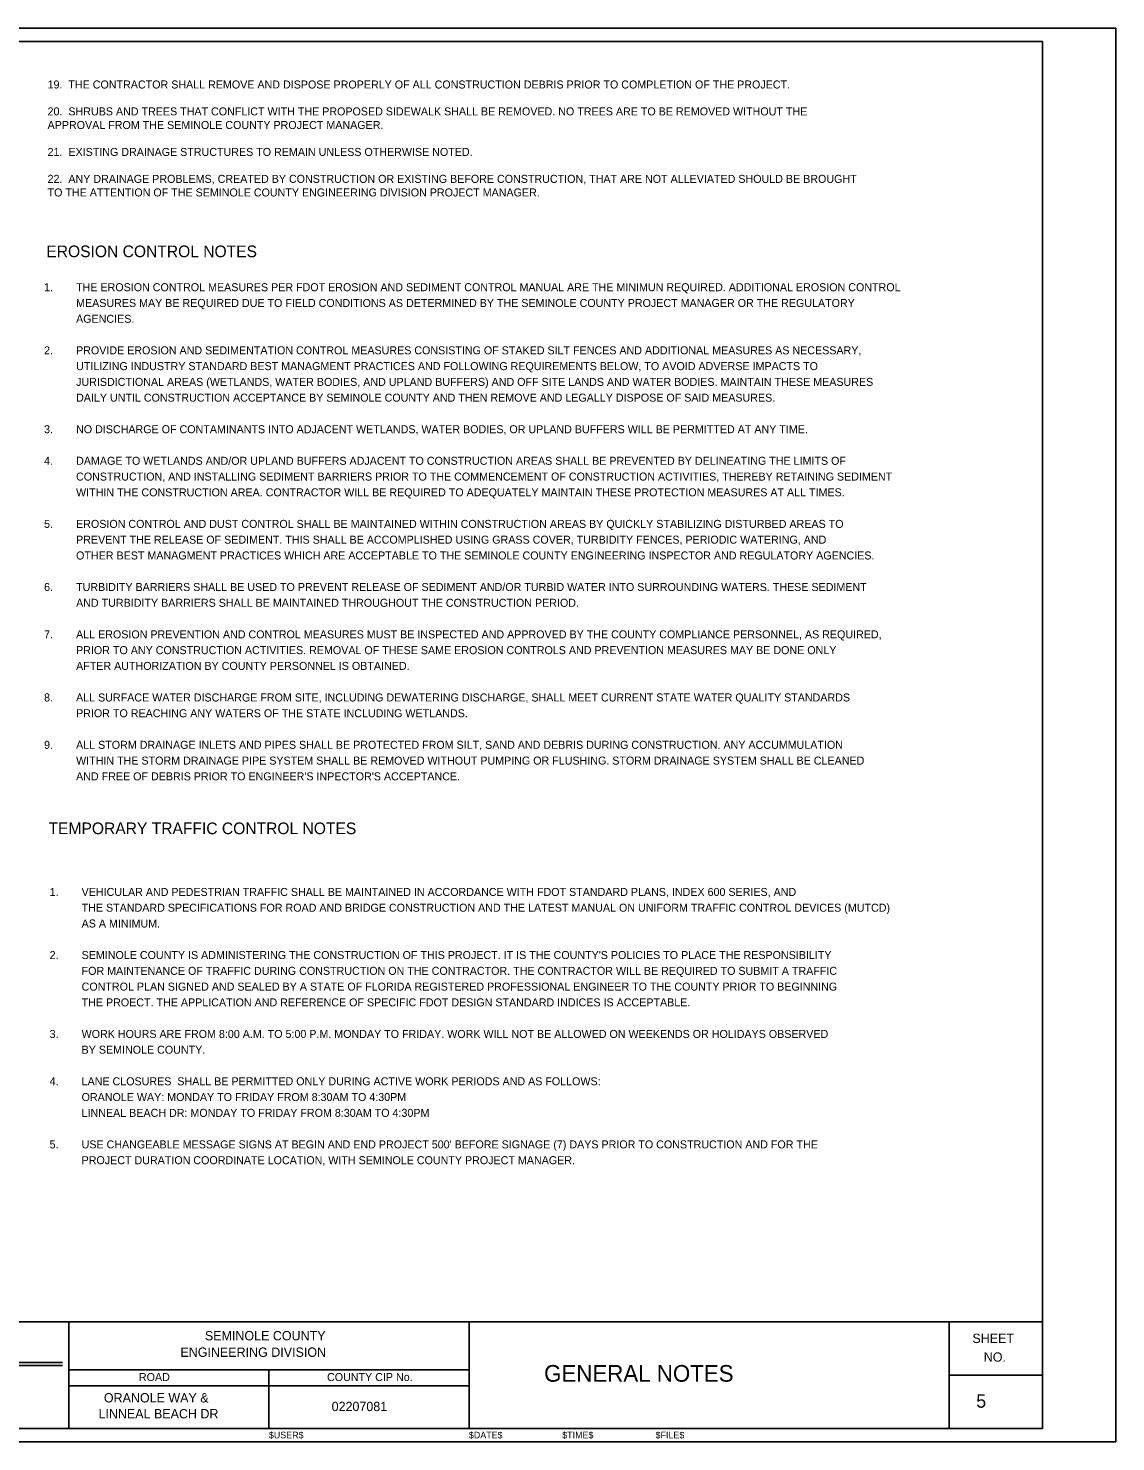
# Model space of a CAD drawing. Extents: x 9949 to 10609, y 9645 to 10069.
# Drawn here: x 10282.6 to 10608.8, y 9645.5 to 10069.5 of the extents above; entities that cross this region are included whole.
import ezdxf

# ---------------------------------------------------------------- set-up
doc = ezdxf.new("R2010")
doc.units = 0
for name, color, linetype in [('Default', 7, 'Continuous'), ('PlotBorder_dp', 7, 'Continuous'), ('SheetBorder_dp', 7, 'Continuous'), ('SheetLines_dp', 7, 'Continuous'), ('TextMinor', 7, 'Continuous'), ('TextMisc', 7, 'Continuous'), ('TextShtNo', 7, 'Continuous')]:
    doc.layers.add(name, color=color, linetype=linetype)

msp = doc.modelspace()

# ---------------------------------------------------------------- linework, layer by layer
at = {"layer": 'PlotBorder_dp'}
msp.add_lwpolyline([(9948.8, 9645.47), (10608.8, 9645.47), (10608.8, 10069.47), (9948.8, 10069.47)], close=True, dxfattribs=at)
at = {"layer": 'SheetBorder_dp'}
for p, q in [((9970.8, 10065.47), (10586.8, 10065.47)), ((10586.8, 10065.47), (10586.8, 9649.47)), ((9970.8, 9681.47), (10586.8, 9681.47)), ((9970.8, 9649.47), (10586.8, 9649.47))]:
    msp.add_line(p, q, dxfattribs=at)
at = {"layer": 'SheetLines_dp'}
for p, q in [((10294.8, 9681.47), (10294.8, 9649.47)), ((10414.8, 9649.47), (10414.8, 9681.47)), ((10558.8, 9649.47), (10558.8, 9681.47)), ((10294.8, 9667.07), (10414.8, 9667.07)), ((10354.8, 9667.07), (10354.8, 9649.47)), ((10558.8, 9665.47), (10586.8, 9665.47)), ((10294.8, 9662.27), (10414.8, 9662.27))]:
    msp.add_line(p, q, dxfattribs=at)
at = {"layer": 'TextMisc'}
for p, q in [((10237.36, 9668.35), (10292.82, 9668.35)), ((10237.44, 9669.25), (10292.9, 9669.25))]:
    msp.add_line(p, q, dxfattribs=at)

# ---------------------------------------------------------------- texts
at = {"layer": 'Default'}
for s, p in [('1. ', (10287.33, 9990.59)), ('THE EROSION CONTROL MEASURES PER FDOT EROSION AND SEDIMENT CONTROL MANUAL ARE THE MINIMUN REQUIRED. ADDITIONAL EROSION CONTROL', (10296.93, 9990.59)), ('MEASURES MAY BE REQUIRED DUE TO FIELD CONDITIONS AS DETERMINED BY THE SEMINOLE COUNTY PROJECT MANAGER OR THE REGULATORY', (10296.93, 9985.86)), ('AGENCIES.', (10296.93, 9981.12)), ('2.', (10287.33, 9971.66)), ('PROVIDE EROSION AND SEDIMENTATION CONTROL MEASURES CONSISTING OF STAKED SILT FENCES AND ADDITIONAL MEASURES AS NECESSARY, ', (10296.93, 9971.66)), ('UTILIZING INDUSTRY STANDARD BEST MANAGMENT PRACTICES AND FOLLOWING REQUIREMENTS BELOW, TO AVOID ADVERSE IMPACTS TO ', (10296.93, 9966.92)), ('JURISDICTIONAL AREAS (WETLANDS, WATER BODIES, AND UPLAND BUFFERS) AND OFF SITE LANDS AND WATER BODIES. MAINTAIN THESE MEASURES ', (10296.93, 9962.19)), ('DAILY UNTIL CONSTRUCTION ACCEPTANCE BY SEMINOLE COUNTY AND THEN REMOVE AND LEGALLY DISPOSE OF SAID MEASURES.', (10296.93, 9957.46)), ('3.', (10287.33, 9947.99)), ('NO DISCHARGE OF CONTAMINANTS INTO ADJACENT WETLANDS, WATER BODIES, OR UPLAND BUFFERS WILL BE PERMITTED AT ANY TIME.', (10296.93, 9947.99)), ('4. ', (10287.33, 9938.52)), ('DAMAGE TO WETLANDS AND/OR UPLAND BUFFERS ADJACENT TO CONSTRUCTION AREAS SHALL BE PREVENTED BY DELINEATING THE LIMITS OF', (10296.93, 9938.52)), ('CONSTRUCTION, AND INSTALLING SEDIMENT BARRIERS PRIOR TO THE COMMENCEMENT OF CONSTRUCTION ACTIVITIES, THEREBY RETAINING SEDIMENT', (10296.93, 9933.79)), ('WITHIN THE CONSTRUCTION AREA. CONTRACTOR WILL BE REQUIRED TO ADEQUATELY MAINTAIN THESE PROTECTION MEASURES AT ALL TIMES.', (10296.93, 9929.06)), ('5.', (10287.33, 9919.59)), ('EROSION CONTROL AND DUST CONTROL SHALL BE MAINTAINED WITHIN CONSTRUCTION AREAS BY QUICKLY STABILIZING DISTURBED AREAS TO', (10296.93, 9919.59)), ('PREVENT THE RELEASE OF SEDIMENT. THIS SHALL BE ACCOMPLISHED USING GRASS COVER, TURBIDITY FENCES, PERIODIC WATERING, AND ', (10296.93, 9914.86)), ('OTHER BEST MANAGMENT PRACTICES WHICH ARE ACCEPTABLE TO THE SEMINOLE COUNTY ENGINEERING INSPECTOR AND REGULATORY AGENCIES.', (10296.93, 9910.12)), ('6.', (10287.33, 9900.66)), ('TURBIDITY BARRIERS SHALL BE USED TO PREVENT RELEASE OF SEDIMENT AND/OR TURBID WATER INTO SURROUNDING WATERS. THESE SEDIMENT', (10296.93, 9900.66)), ('AND TURBIDITY BARRIERS SHALL BE MAINTAINED THROUGHOUT THE CONSTRUCTION PERIOD.', (10296.93, 9895.92)), ('7.', (10287.33, 9886.46)), ('ALL EROSION PREVENTION AND CONTROL MEASURES MUST BE INSPECTED AND APPROVED BY THE COUNTY COMPLIANCE PERSONNEL, AS REQUIRED,', (10296.93, 9886.46)), ('PRIOR TO ANY CONSTRUCTION ACTIVITIES. REMOVAL OF THESE SAME EROSION CONTROLS AND PREVENTION MEASURES MAY BE DONE ONLY', (10296.93, 9881.72)), ('AFTER AUTHORIZATION BY COUNTY PERSONNEL IS OBTAINED.', (10296.93, 9876.99)), ('8.', (10287.33, 9867.52)), ('ALL SURFACE WATER DISCHARGE FROM SITE, INCLUDING DEWATERING DISCHARGE, SHALL MEET CURRENT STATE WATER QUALITY STANDARDS', (10296.93, 9867.52)), ('PRIOR TO REACHING ANY WATERS OF THE STATE INCLUDING WETLANDS.', (10296.93, 9862.79)), ('9.', (10287.33, 9853.32)), ('ALL STORM DRAINAGE INLETS AND PIPES SHALL BE PROTECTED FROM SILT, SAND AND DEBRIS DURING CONSTRUCTION. ANY ACCUMMULATION ', (10296.93, 9853.32)), ('WITHIN THE STORM DRAINAGE PIPE SYSTEM SHALL BE REMOVED WITHOUT PUMPING OR FLUSHING. STORM DRAINAGE SYSTEM SHALL BE CLEANED', (10296.93, 9848.59)), ("AND FREE OF DEBRIS PRIOR TO ENGINEER'S INPECTOR'S ACCEPTANCE.", (10296.93, 9843.86)), ('1. ', (10288.99, 9809.19)), ('VEHICULAR AND PEDESTRIAN TRAFFIC SHALL BE MAINTAINED IN ACCORDANCE WITH FDOT STANDARD PLANS, INDEX 600 SERIES, AND  ', (10298.59, 9809.19)), ('THE STANDARD SPECIFICATIONS FOR ROAD AND BRIDGE CONSTRUCTION AND THE LATEST MANUAL ON UNIFORM TRAFFIC CONTROL DEVICES (MUTCD) ', (10298.59, 9804.46)), ('AS A MINIMUM.', (10298.59, 9799.72)), ('2.', (10288.99, 9790.26)), ("SEMINOLE COUNTY IS ADMINISTERING THE CONSTRUCTION OF THIS PROJECT. IT IS THE COUNTY'S POLICIES TO PLACE THE RESPONSIBILITY", (10298.59, 9790.26)), ('FOR MAINTENANCE OF TRAFFIC DURING CONSTRUCTION ON THE CONTRACTOR. THE CONTRACTOR WILL BE REQUIRED TO SUBMIT A TRAFFIC ', (10298.59, 9785.52)), ('CONTROL PLAN SIGNED AND SEALED BY A STATE OF FLORIDA REGISTERED PROFESSIONAL ENGINEER TO THE COUNTY PRIOR TO BEGINNING ', (10298.59, 9780.79)), ('THE PROECT. THE APPLICATION AND REFERENCE OF SPECIFIC FDOT DESIGN STANDARD INDICES IS ACCEPTABLE.', (10298.59, 9776.06)), ('3.', (10288.99, 9766.59)), ('WORK HOURS ARE FROM 8:00 A.M. TO 5:00 P.M. MONDAY TO FRIDAY. WORK WILL NOT BE ALLOWED ON WEEKENDS OR HOLIDAYS OBSERVED ', (10298.59, 9766.59)), ('BY SEMINOLE COUNTY.', (10298.59, 9761.86)), ('4.', (10288.99, 9752.39)), ('LANE CLOSURES  SHALL BE PERMITTED ONLY DURING ACTIVE WORK PERIODS AND AS FOLLOWS:', (10298.59, 9752.39)), ('ORANOLE WAY: MONDAY TO FRIDAY FROM 8:30AM TO 4:30PM', (10298.59, 9747.66)), ('LINNEAL BEACH DR: MONDAY TO FRIDAY FROM 8:30AM TO 4:30PM', (10298.59, 9742.92)), ('5.  ', (10288.99, 9733.46)), ("USE CHANGEABLE MESSAGE SIGNS AT BEGIN AND END PROJECT 500' BEFORE SIGNAGE (7) DAYS PRIOR TO CONSTRUCTION AND FOR THE ", (10298.59, 9733.46)), ('PROJECT DURATION COORDINATE LOCATION, WITH SEMINOLE COUNTY PROJECT MANAGER.', (10298.59, 9728.72))]:
    msp.add_text(s, height=2.4, dxfattribs=at).set_placement(p)
at = {"layer": 'TextMinor'}
for s, p in [('$USER$', (10354.76, 9646.47)), ('$DATE$', (10414.76, 9646.47)), ('$TIME$', (10442.76, 9646.47)), ('$FILE$', (10470.76, 9646.47))]:
    msp.add_text(s, height=2, rotation=360, dxfattribs=at).set_placement(p)
at = {"layer": 'TextMisc'}
for s, height, p in [('19.  THE CONTRACTOR SHALL REMOVE AND DISPOSE PROPERLY OF ALL CONSTRUCTION DEBRIS PRIOR TO COMPLETION OF THE PROJECT.', 2.4, (10288.38, 10051.4)), ('20.  SHRUBS AND TREES THAT CONFLICT WITH THE PROPOSED SIDEWALK SHALL BE REMOVED. NO TREES ARE TO BE REMOVED WITHOUT THE ', 2.4, (10288.38, 10043.33)), ('APPROVAL FROM THE SEMINOLE COUNTY PROJECT MANAGER.', 2.4, (10288.38, 10039.25)), ('21.  EXISTING DRAINAGE STRUCTURES TO REMAIN UNLESS OTHERWISE NOTED.', 2.4, (10288.38, 10031.17)), ('22.  ANY DRAINAGE PROBLEMS, CREATED BY CONSTRUCTION OR EXISTING BEFORE CONSTRUCTION, THAT ARE NOT ALLEVIATED SHOULD BE BROUGHT ', 2.4, (10288.38, 10023.09)), ('TO THE ATTENTION OF THE SEMINOLE COUNTY ENGINEERING DIVISION PROJECT MANAGER.', 2.4, (10288.38, 10019.02)), ('EROSION CONTROL NOTES', 3.5, (10288.01, 10000.8)), ('TEMPORARY TRAFFIC CONTROL NOTES', 3.5, (10288.67, 9827.72)), ('     GENERAL NOTES      ', 5, (10428.03, 9663.47))]:
    msp.add_text(s, height=height, dxfattribs=at).set_placement(p)
for s, height, rotation, p in [('SEMINOLE COUNTY', 2.8, 360, (10335.57, 9675.87)), ('SHEET', 2.8, 359.8607, (10565.79, 9675.09)), ('ENGINEERING DIVISION', 2.8, 360, (10328.23, 9670.93)), ('NO.', 2.8, 359.8607, (10569.21, 9669.48)), ('ROAD', 2.4, 360, (10315.78, 9663.67)), ('COUNTY CIP No.', 2.4, 360, (10372.21, 9663.67)), ('ORANOLE WAY & ', 2.8, 360, (10305.27, 9657.25)), (' LINNEAL BEACH DR', 2.8, 360, (10302.61, 9652.47)), ('   02207081   ', 2.8, 360, (10370.47, 9654.65))]:
    msp.add_text(s, height=height, rotation=rotation, dxfattribs=at).set_placement(p)
at = {"layer": 'TextShtNo'}
msp.add_text('  5   ', height=4, dxfattribs=at).set_placement((10563.99, 9655.67))

doc.saveas('drawing.dxf')
